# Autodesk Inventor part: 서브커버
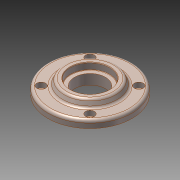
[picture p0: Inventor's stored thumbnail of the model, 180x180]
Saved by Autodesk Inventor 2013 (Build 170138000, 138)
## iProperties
Created: 2013-01
Part Number: 서브커버
Document SubType Name: Modeling
Designer: 한국산업디자인학원[gmhk.co.kr]
Density: 7.25 g/cm^3
Material: 주철
Mass: 439.929 g
Surface Area: 178.476 cm^2
Volume: 60.6798 cm^3
Author: 한국산업디자인학원[gmhk.co.kr]
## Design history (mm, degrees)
sketch "스케치2"
  geometry: L1 (-45, 0)-(0, 0); L2 (-25.784, -7)-(25.784, -7) reference; L3 (0, -7)-(0, 15); L4 (-31, -23)-(-31, 0) reference; L5 (-26.5, -7)-(-26.5, -3); L6 (-26.5, -3)-(0, -3); L7 (-26.5, -7)-(-31, -7); L8 (-31, 0)-(-45, 0); L9 (-45, 0)-(-45, 8); L10 (-45, 8)-(-30, 8); L11 (-30, 8)-(-26.736, 15); L12 (-26.736, 15)-(0, 15)
  constraints: 25 end point, 6 perpendicular, 3 point on line, 1 collinear, 1 horizontal, 1 midpoint, 1 parallel, 1 vertical, 3 other
  dimensions: "d0" = 53 diameter of L5 L3; "d1" = 4 distance between parallel lines of L6 L2; "d2" = 8 distance between parallel lines of L10 L1; "d3" = 7 distance between parallel lines of L12 L10; "d4" = 60 diameter of L10.end L3; "d5" = 115 deg angle of L11 L10; "d27" = 90 diameter of L9 L3
revolve "회전1" sketch "스케치2" stored, may be unused: angle "d6" = 90 deg
hole "구멍1" diameter "d9" = 33; stored, may be unused: countersink angle "d13" = 90 deg, drill point angle "d15" = 118 deg; dims "d10" = 6, "d11" = 42, "d12" = 7.3, "d14" = 8, "d38" = 10, "d39" = 10
fillet "모깎기1" dims "d16" = 3
chamfer "모따기1" distance "d17" = 0.7; stored, may be unused: second distance "d18" = 2, angle "d19" = 30 deg
sketch "스케치3"
  geometry: C1 r 2.067 at (26.163, 26.163) reference; 1 further point
hole "구멍2" sketch "스케치3" at (26.163, 26.163) diameter "d20" = 5.4; stored, may be unused: countersink angle "d24" = 90 deg, drill point angle "d26" = 118 deg; dims "d21" = 6, "d22" = 9.5, "d23" = 5.5, "d25" = 8
fillet "모깎기2" dims "d31" = 0.3
fillet "모깎기3" dims "d32" = 3
chamfer "모따기2" distance "d35" = 1; stored, may be unused: second distance "d36" = 2, angle "d37" = 45 deg
node "솔리드1"
pattern_circular "원형 패턴1" dims angle "d29" = 360 deg
node "참조3"
